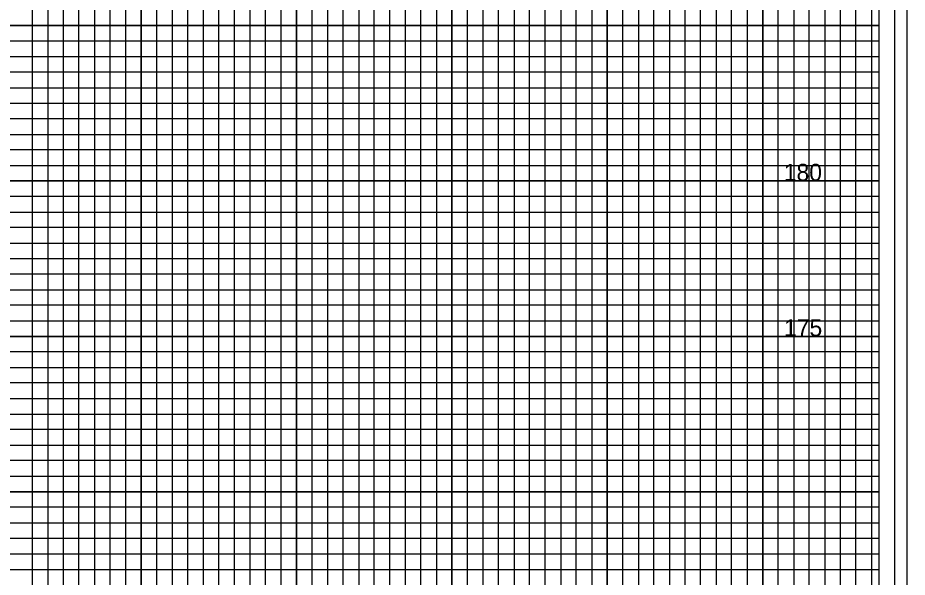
# Model space of a CAD drawing. Extents: x -4 to 103, y -2 to 280.
# Drawn here: x 74.78 to 103.4, y 103.08 to 121.08 of the extents above; entities that cross this region are included whole.
import ezdxf

# ---------------------------------------------------------------- set-up
doc = ezdxf.new("R2010")
doc.units = 0
for name, color, linetype in [('Exist XS Center Line Elevation Label', 7, 'Continuous'), ('Old_Level_63', 7, 'Continuous'), ('Prop XS Dump Level', 7, 'Continuous'), ('Prop XS SE Text', 7, 'Continuous'), ('Prop XS Subgrade Earthwork', 7, 'Continuous'), ('Sheet Plot Border Inside CELL', 7, 'Continuous'), ('Sheet Plot Border Outside CELL', 7, 'Continuous')]:
    doc.layers.add(name, color=color, linetype=linetype)

msp = doc.modelspace()

# ---------------------------------------------------------------- linework, layer by layer
at = {"layer": 'Exist XS Center Line Elevation Label'}
for points in [[(91.25, 70.825), (91.25, 134.25), (93.75, 134.25), (93.75, 70.825)], [(96.25, 70.825), (96.25, 134.25), (98.75, 134.25), (98.75, 70.825)], [(101.25, 70.825), (101.25, 134.25)], [(76.25, 70.825), (76.25, 132.825), (78.75, 132.825), (78.75, 70.825)], [(81.25, 70.825), (81.25, 132.825), (83.75, 132.825), (83.75, 70.825)], [(86.25, 70.825), (86.25, 132.825), (88.75, 132.825), (88.75, 70.825)], [(0, 118.325), (102.5, 118.325), (102.5, 120.825), (0, 120.825)], [(0, 113.325), (102.5, 113.325), (102.5, 115.825), (0, 115.825)], [(0, 108.325), (102.5, 108.325), (102.5, 110.825), (0, 110.825)], [(0, 103.325), (102.5, 103.325), (102.5, 105.825), (0, 105.825)]]:
    msp.add_lwpolyline(points, dxfattribs=at)
at = {"layer": 'Old_Level_63'}
msp.add_lwpolyline([(102.5, 135.825), (0, 135.825), (0, 70.825), (102.5, 70.825)], close=True, dxfattribs=at)
at = {"layer": 'Prop XS Dump Level'}
for p, q in [((91.25, 70.825), (91.25, 134.25)), ((93.75, 70.825), (93.75, 134.25)), ((96.25, 70.825), (96.25, 134.25)), ((98.75, 70.825), (98.75, 134.25)), ((101.25, 70.825), (101.25, 134.25)), ((76.25, 70.825), (76.25, 132.825)), ((78.75, 70.825), (78.75, 132.825)), ((81.25, 70.825), (81.25, 132.825)), ((83.75, 70.825), (83.75, 132.825)), ((86.25, 70.825), (86.25, 132.825)), ((88.75, 70.825), (88.75, 132.825)), ((0, 120.825), (102.5, 120.825)), ((0, 118.325), (102.5, 118.325)), ((0, 115.825), (102.5, 115.825)), ((0, 113.325), (102.5, 113.325)), ((0, 110.825), (102.5, 110.825)), ((0, 108.325), (102.5, 108.325)), ((0, 105.825), (102.5, 105.825)), ((0, 103.325), (102.5, 103.325))]:
    msp.add_line(p, q, dxfattribs=at)
at = {"layer": 'Prop XS SE Text'}
for points in [[(90.25, 70.825), (90.25, 134.25), (90.75, 134.25), (90.75, 70.825)], [(91.75, 70.825), (91.75, 134.25), (92.25, 134.25), (92.25, 70.825)], [(92.75, 70.825), (92.75, 134.25), (93.25, 134.25), (93.25, 70.825)], [(94.25, 70.825), (94.25, 134.25), (94.75, 134.25), (94.75, 70.825)], [(95.25, 70.825), (95.25, 134.25), (95.75, 134.25), (95.75, 70.825)], [(96.75, 70.825), (96.75, 134.25), (97.25, 134.25), (97.25, 70.825)], [(97.75, 70.825), (97.75, 134.25), (98.25, 134.25), (98.25, 70.825)], [(99.25, 70.825), (99.25, 134.25), (99.75, 134.25), (99.75, 70.825)], [(100.25, 70.825), (100.25, 134.25)], [(100.25, 134.25), (100.75, 134.25), (100.75, 70.825), (101.75, 70.825), (101.75, 134.25), (102.25, 134.25), (102.25, 70.825)], [(75.25, 70.825), (75.25, 132.825), (75.75, 132.825), (75.75, 70.825)], [(76.75, 70.825), (76.75, 132.825), (77.25, 132.825), (77.25, 70.825)], [(77.75, 70.825), (77.75, 132.825), (78.25, 132.825), (78.25, 70.825)], [(79.25, 70.825), (79.25, 132.825), (79.75, 132.825), (79.75, 70.825)], [(80.25, 70.825), (80.25, 132.825), (80.75, 132.825), (80.75, 70.825)], [(81.75, 70.825), (81.75, 132.825), (82.25, 132.825), (82.25, 70.825)], [(82.75, 70.825), (82.75, 132.825), (83.25, 132.825), (83.25, 70.825)], [(84.25, 70.825), (84.25, 132.825), (84.75, 132.825), (84.75, 70.825)], [(85.25, 70.825), (85.25, 132.825), (85.75, 132.825), (85.75, 70.825)], [(86.75, 70.825), (86.75, 132.825), (87.25, 132.825), (87.25, 70.825)], [(87.75, 70.825), (87.75, 132.825), (88.25, 132.825), (88.25, 70.825)], [(89.25, 70.825), (89.25, 132.825), (89.75, 132.825), (89.75, 70.825)], [(0, 119.825), (102.5, 119.825), (102.5, 120.325), (0, 120.325)], [(0, 118.825), (102.5, 118.825), (102.5, 119.325), (0, 119.325)], [(0, 117.325), (102.5, 117.325), (102.5, 117.825), (0, 117.825)], [(0, 116.325), (102.5, 116.325), (102.5, 116.825), (0, 116.825)], [(0, 114.825), (102.5, 114.825), (102.5, 115.325), (0, 115.325)], [(0, 113.825), (102.5, 113.825), (102.5, 114.325), (0, 114.325)], [(0, 112.325), (102.5, 112.325), (102.5, 112.825), (0, 112.825)], [(0, 111.325), (102.5, 111.325), (102.5, 111.825), (0, 111.825)], [(0, 109.825), (102.5, 109.825), (102.5, 110.325), (0, 110.325)], [(0, 108.825), (102.5, 108.825), (102.5, 109.325), (0, 109.325)], [(0, 107.325), (102.5, 107.325), (102.5, 107.825), (0, 107.825)], [(0, 106.325), (102.5, 106.325), (102.5, 106.825), (0, 106.825)], [(0, 104.825), (102.5, 104.825), (102.5, 105.325), (0, 105.325)], [(0, 103.825), (102.5, 103.825), (102.5, 104.325), (0, 104.325)]]:
    msp.add_lwpolyline(points, dxfattribs=at)
at = {"layer": 'Sheet Plot Border Inside CELL'}
msp.add_lwpolyline([(103, 136.825), (-2.8, 136.825), (-2.8, 69.825), (103, 69.825)], close=True, dxfattribs=at)
at = {"layer": 'Sheet Plot Border Outside CELL'}
msp.add_lwpolyline([(103.4, 138.225), (-3.5, 138.225), (-3.5, 68.4), (103.4, 68.4)], close=True, dxfattribs=at)

# ---------------------------------------------------------------- texts
at = {"layer": 'Prop XS Subgrade Earthwork'}
for s, p in [('180', (99.43, 115.825)), ('175', (99.438, 110.825))]:
    msp.add_text(s, height=0.55, dxfattribs=at).set_placement(p)

doc.saveas('drawing.dxf')
